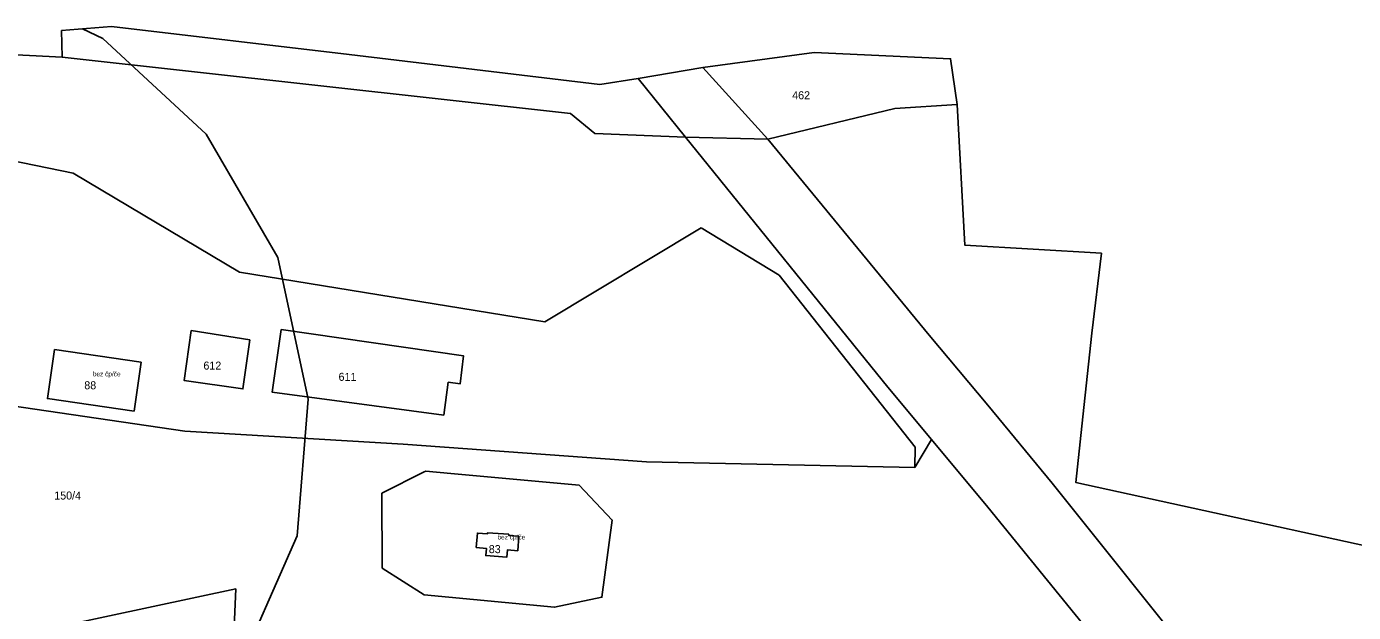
# Model space of a CAD drawing. Extents: x -882150 to -879379, y -1022570 to -1019819.
# Drawn here: x -880321.1 to -880039.3, y -1020139.9 to -1020015.4 of the extents above; entities that cross this region are included whole.
import ezdxf

# ---------------------------------------------------------------- set-up
doc = ezdxf.new("R2010")
doc.units = 0
for name, color, linetype in [('Definiční body', 7, 'Continuous'), ('Hranice parcel', 7, 'Continuous'), ('Parcelní čísla', 7, 'Continuous'), ('Polygon budovy', 7, 'Continuous'), ('Vnitřní kresba', 7, 'Continuous')]:
    doc.layers.add(name, color=color, linetype=linetype)

msp = doc.modelspace()

# ---------------------------------------------------------------- linework, layer by layer
at = {"layer": 'Hranice parcel'}
for p, q in [((-880313.68, -1020016.21), (-880303.06, -1020015.38)), ((-880313.53, -1020021.89), (-880313.68, -1020016.21)), ((-880339.38, -1020020.63), (-880313.53, -1020021.89)), ((-880191.22, -1020026.44), (-880177.44, -1020024.1)), ((-880163.65, -1020039.32), (-880181.11, -1020038.89)), ((-880276.63, -1020134.84), (-880277.64, -1020157.16))]:
    msp.add_line(p, q, dxfattribs=at)
for points in [[(-880303.06, -1020015.38), (-880252.6, -1020021.33), (-880199.31, -1020027.67), (-880191.22, -1020026.44)], [(-880313.53, -1020021.89), (-880205.55, -1020033.87), (-880200.38, -1020038.13), (-880181.11, -1020038.89)], [(-880177.44, -1020024.1), (-880153.83, -1020020.89), (-880124.84, -1020022.22), (-880123.46, -1020031.92)], [(-880123.46, -1020031.92), (-880136.65, -1020032.77), (-880163.65, -1020039.32)], [(-880123.46, -1020031.92), (-880121.79, -1020061.83), (-880092.81, -1020063.54), (-880094.81, -1020080.54), (-880096.99, -1020100.28)], [(-880181.11, -1020038.89), (-880138.13, -1020091.96), (-880128.9, -1020103.08)], [(-880163.65, -1020039.32), (-880129.35, -1020080.97), (-880116.9, -1020095.84), (-880103.23, -1020112.38), (-880070.49, -1020153.39), (-880028.73, -1020206.59)], [(-880128.9, -1020103.08), (-880132.45, -1020109.03), (-880189.45, -1020107.84), (-880241.14, -1020104.11), (-880287.51, -1020101.32), (-880356.63, -1020091.22), (-880430.92, -1020082.98), (-880459.65, -1020079.14), (-880540.91, -1020069)], [(-880273.66, -1020081.92), (-880275.17, -1020092.35), (-880287.64, -1020090.56), (-880286.12, -1020079.97), (-880273.66, -1020081.92)], [(-880231.58, -1020090.94), (-880232.48, -1020097.91), (-880268.98, -1020093.02), (-880267.01, -1020079.77), (-880228.29, -1020085.37), (-880228.99, -1020091.28), (-880231.58, -1020090.94)], [(-880315.18, -1020083.99), (-880316.67, -1020094.43), (-880298.27, -1020097.07), (-880296.78, -1020086.7), (-880315.18, -1020083.99)], [(-880096.99, -1020100.28), (-880098.21, -1020112.28), (-880006.99, -1020132.18), (-879991.06, -1020130.47)], [(-880502.38, -1020102.49), (-880497.06, -1020107.99), (-880478.95, -1020132.59), (-880425.73, -1020148.42), (-880407.16, -1020151.31), (-880349.97, -1020150.48), (-880276.63, -1020134.84)], [(-880079.85, -1020163.08), (-880116.94, -1020117.46), (-880128.9, -1020103.08)], [(-880236.63, -1020109.97), (-880245.65, -1020114.53), (-880245.59, -1020130.44), (-880236.66, -1020136.12), (-880208.94, -1020138.76), (-880198.91, -1020136.64), (-880196.71, -1020120.23), (-880203.71, -1020112.84), (-880230.98, -1020110.31), (-880236.31, -1020109.81), (-880236.63, -1020109.97)]]:
    msp.add_lwpolyline(points, dxfattribs=at)
at = {"layer": 'Polygon budovy'}
for points in [[(-880315.18, -1020083.99), (-880316.67, -1020094.43), (-880298.27, -1020097.07), (-880296.78, -1020086.7)], [(-880216.79, -1020126.73), (-880216.55, -1020123.67), (-880218.7, -1020123.5), (-880218.68, -1020123.25), (-880223.19, -1020122.92), (-880223.22, -1020123.16), (-880225.35, -1020122.99), (-880225.58, -1020126.04), (-880223.44, -1020126.25), (-880223.59, -1020127.76), (-880219.11, -1020128.11), (-880218.99, -1020126.56)]]:
    msp.add_lwpolyline(points, close=True, dxfattribs=at)
at = {"layer": 'Vnitřní kresba'}
for p, q in [((-880309.23, -1020015.86), (-880304.9, -1020017.91)), ((-880177.44, -1020024.1), (-880163.65, -1020039.32)), ((-880191.22, -1020026.44), (-880181.11, -1020038.89)), ((-880379.69, -1020032.59), (-880311.22, -1020046.5)), ((-880311.22, -1020046.5), (-880275.89, -1020067.58)), ((-880211, -1020078.14), (-880177.81, -1020058.11)), ((-880177.81, -1020058.11), (-880161.24, -1020068.23)), ((-880275.89, -1020067.58), (-880211, -1020078.14)), ((-880161.24, -1020068.23), (-880132.37, -1020104.75)), ((-880132.45, -1020109.03), (-880132.37, -1020104.75)), ((-880225.58, -1020126.04), (-880225.35, -1020122.99)), ((-880225.35, -1020122.99), (-880223.22, -1020123.16)), ((-880223.22, -1020123.16), (-880223.19, -1020122.92)), ((-880223.19, -1020122.92), (-880218.68, -1020123.25)), ((-880218.68, -1020123.25), (-880218.7, -1020123.5)), ((-880218.7, -1020123.5), (-880216.55, -1020123.67)), ((-880216.55, -1020123.67), (-880216.79, -1020126.73)), ((-880223.44, -1020126.25), (-880225.58, -1020126.04)), ((-880223.59, -1020127.76), (-880223.44, -1020126.25)), ((-880219.11, -1020128.11), (-880223.59, -1020127.76)), ((-880218.99, -1020126.56), (-880219.11, -1020128.11)), ((-880216.79, -1020126.73), (-880218.99, -1020126.56))]:
    msp.add_line(p, q, dxfattribs=at)
for points in [[(-880263.6, -1020123.56), (-880261.31, -1020094.54), (-880267.72, -1020064.46), (-880283, -1020038.24), (-880304.9, -1020017.91)], [(-880293.2, -1020174.89), (-880277.57, -1020155.32), (-880263.6, -1020123.56)]]:
    msp.add_lwpolyline(points, dxfattribs=at)

# ---------------------------------------------------------------- texts
at = {"layer": 'Definiční body'}
for p in [(-880307.04, -1020089.69), (-880221.09, -1020124.35)]:
    msp.add_text('bez čp/če', height=1, dxfattribs=at).set_placement(p)
at = {"layer": 'Parcelní čísla'}
for s, p in [('462', (-880158.48, -1020030.83)), ('612', (-880283.553, -1020088.26)), ('611', (-880254.839, -1020090.65)), ('88', (-880308.852, -1020092.44)), ('150/4', (-880315.232, -1020115.86)), ('83', (-880222.934, -1020127.25))]:
    msp.add_text(s, height=1.7, dxfattribs=at).set_placement(p)

doc.saveas('drawing.dxf')
